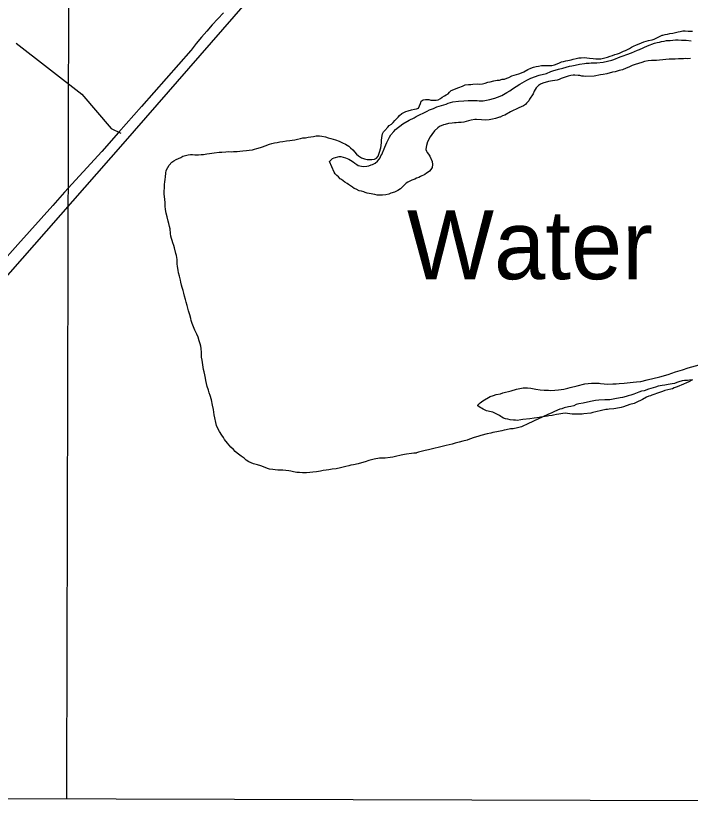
# Model space of a CAD drawing. Extents: x 3161514 to 3199414, y 831166 to 856601.
# Drawn here: x 3191795 to 3192773, y 836546 to 837696 of the extents above; entities that cross this region are included whole.
import ezdxf

# ---------------------------------------------------------------- set-up
doc = ezdxf.new("R2010")
doc.units = 0
for name, color, linetype in [('V-GRID-FRAM', 7, 'Continuous'), ('V-GRID-MAJR', 7, 'Continuous'), ('V-RIVR-IDEN', 7, 'Continuous'), ('V-ROAD-CNTR', 7, 'Continuous'), ('V-SITE-VEGE', 7, 'Continuous'), ('V-TOPO-SHOR', 7, 'Continuous')]:
    doc.layers.add(name, color=color, linetype=linetype)

msp = doc.modelspace()

# ---------------------------------------------------------------- linework, layer by layer
at = {"layer": 'V-GRID-FRAM'}
msp.add_lwpolyline([(3165761, 854820), (3197144.3, 854733.3), (3197102, 836546.1), (3165702.9, 836632.9), (3165761, 854820)], dxfattribs=at)
at = {"layer": 'V-GRID-MAJR'}
msp.add_spline([(3191868.8, 836560.6), (3191883.8, 842621), (3191898.8, 848683.4), (3191913.8, 854745.9), (3191913.8, 854747.8)], degree=3, dxfattribs=at)
at = {"layer": 'V-ROAD-CNTR'}
msp.add_lwpolyline([(3191529.5, 837031.7), (3191950.4, 837510.3), (3192561.4, 838211.2)], dxfattribs=at)
at = {"layer": 'V-SITE-VEGE'}
for points in [[(3192256.6, 837469), (3192250, 837484.8), (3192251.5, 837486.7), (3192254.3, 837488.9), (3192256.3, 837490), (3192263.6, 837491.9), (3192266.4, 837491.9), (3192273.1, 837489.8), (3192277.9, 837488.1), (3192280.1, 837486.6), (3192284, 837484.3), (3192286.5, 837482.3), (3192289.3, 837480.3), (3192291.5, 837478.9), (3192293.7, 837478.3), (3192298.5, 837477.4), (3192304.1, 837477.9), (3192306.6, 837478.4), (3192310.3, 837479.5), (3192312.3, 837480.3), (3192315.9, 837482.2), (3192319.3, 837485), (3192321.6, 837487.8), (3192323, 837489.7), (3192324.2, 837492.8), (3192325.6, 837494.7), (3192330.2, 837505.3), (3192332.9, 837512), (3192334.3, 837515.1), (3192336.6, 837519.6), (3192338.6, 837523.2), (3192342.9, 837528.2), (3192345.4, 837530.7), (3192356.2, 837539), (3192365.5, 837544.4), (3192372.6, 837548), (3192375.4, 837549.9), (3192391.2, 837557.3), (3192394.6, 837559.2), (3192400.8, 837561.4), (3192405.6, 837563.6), (3192412.4, 837565.7), (3192419.1, 837567.6), (3192421.6, 837569), (3192428.4, 837570.8), (3192436.6, 837572.1), (3192444.7, 837572.6), (3192450.6, 837572.8), (3192454, 837572.8), (3192459, 837573), (3192464, 837572.9), (3192466.6, 837572.6), (3192472.5, 837572.3), (3192482.3, 837574.4), (3192487.4, 837575.7), (3192489.6, 837576.5), (3192493.3, 837577.6), (3192499.5, 837580.3), (3192504.3, 837583.3), (3192506.8, 837584.4), (3192511.1, 837586.9), (3192515.3, 837589.7), (3192525.8, 837596.8), (3192528.9, 837598.5), (3192535.7, 837602.6), (3192541.9, 837605.3), (3192554, 837609.6), (3192564.4, 837612), (3192570.9, 837614.8), (3192573.7, 837615.8), (3192581.6, 837618.3), (3192588.1, 837619.6), (3192597.9, 837622.5), (3192601, 837623.1), (3192605.8, 837624.4), (3192612.2, 837625.4), (3192619.3, 837626.8), (3192622.1, 837627), (3192626.3, 837626.9), (3192629.1, 837627.5), (3192633.9, 837627.7), (3192637.5, 837627.6), (3192646.5, 837628.7), (3192659.2, 837631.6), (3192662, 837632.4), (3192671.3, 837636.2), (3192675.5, 837637.5), (3192680.9, 837639.7), (3192687.6, 837641.9), (3192696.4, 837646), (3192699.2, 837647.1), (3192710.8, 837652), (3192720.9, 837655.8), (3192725.1, 837656.8), (3192728.2, 837657.3), (3192731.3, 837658.4), (3192735.2, 837658.9), (3192738.6, 837659.7), (3192743.7, 837660), (3192751.5, 837660.7), (3192755.2, 837660.9)], [(3192755.2, 837660.9), (3192760.2, 837660.6), (3192763.9, 837660.5), (3192767, 837660.2), (3192774, 837659.3)], [(3192773.3, 837633.8), (3192769.1, 837633.5), (3192765.8, 837633.6), (3192763, 837633.3), (3192755.7, 837633.2), (3192751.2, 837632.9), (3192748.4, 837633), (3192744.7, 837632.7), (3192742.5, 837632.8), (3192728.4, 837631.3), (3192723.9, 837631), (3192721.7, 837631.1), (3192719.2, 837630.8), (3192716.9, 837630.8), (3192711.6, 837630.4), (3192706.5, 837629.3), (3192702.6, 837628.2), (3192693, 837625.3), (3192688.8, 837623.6), (3192684, 837621.4), (3192680.1, 837619.8), (3192674.4, 837617.6), (3192669.6, 837616.3), (3192667.1, 837615.5), (3192664, 837614.7), (3192660.1, 837613.9), (3192651.9, 837611.8), (3192646.6, 837610.7), (3192642.9, 837610.2), (3192633.6, 837608.3), (3192621.6, 837607.7), (3192617.9, 837608), (3192615.7, 837608.3), (3192612.9, 837609.2), (3192610.1, 837609.2), (3192605.3, 837609.5), (3192603.1, 837609.6), (3192599.7, 837609.1), (3192595.8, 837608), (3192585.6, 837604.7)], [(3192585.6, 837604.7), (3192582.8, 837603.4), (3192580, 837602.6), (3192573.2, 837601.3), (3192567.1, 837600.5), (3192558.9, 837598.1), (3192555.5, 837596.7), (3192553, 837594.8), (3192549.5, 837591.2), (3192546.4, 837586.5), (3192545, 837582.8), (3192539.8, 837574.8), (3192538.9, 837572.5), (3192535.5, 837568.9), (3192533.8, 837567.3), (3192531.3, 837565.3), (3192524.5, 837562.1), (3192519.7, 837560.1), (3192517.2, 837558.8), (3192512.1, 837556.6), (3192504.2, 837551.9), (3192500.5, 837550.6), (3192497.1, 837548.9), (3192496.3, 837548.7), (3192494.6, 837548.4), (3192490.6, 837546.8), (3192486.1, 837545.7), (3192481.1, 837544.9), (3192475.7, 837544.4), (3192470.4, 837544.8), (3192463.1, 837545.4), (3192460.3, 837545.5), (3192455.3, 837544.4), (3192451.3, 837543.3), (3192447.7, 837542.6), (3192444.6, 837541.8), (3192440.6, 837541.2), (3192436.7, 837541), (3192433.3, 837540.5), (3192430.8, 837540.5), (3192427.7, 837540), (3192422.1, 837539.5), (3192417.3, 837538.2), (3192415.1, 837537.6), (3192409.4, 837535.5), (3192406.9, 837533.5), (3192402.1, 837528.8), (3192398.1, 837523.6), (3192395.8, 837520.2), (3192392.1, 837513.3), (3192390.3, 837507.9), (3192389.7, 837505.1), (3192389.4, 837501.8), (3192390.2, 837499.5), (3192391.3, 837497.6), (3192393.5, 837495), (3192395.1, 837492.5), (3192398.4, 837484.8), (3192398.9, 837480.4), (3192398.6, 837476.1), (3192396.9, 837473.1), (3192394.6, 837470.6), (3192392.6, 837468.9), (3192390.6, 837467.8), (3192387.8, 837465.9), (3192381.6, 837462.6), (3192379.3, 837461.2), (3192376, 837460.2), (3192373.4, 837459.1), (3192369.2, 837457.4), (3192363.3, 837454.4), (3192361, 837453.1), (3192357.6, 837450), (3192352.5, 837445), (3192348.8, 837442.6), (3192344, 837440.1), (3192338.6, 837438.5), (3192335.8, 837437.4), (3192331.6, 837436.1), (3192326.8, 837435.6), (3192322.6, 837435.6), (3192319, 837435.9), (3192315.6, 837436.8), (3192307.5, 837438), (3192304.2, 837438.9), (3192301.4, 837439.5), (3192299.4, 837440.4), (3192296.1, 837441.6), (3192293, 837442.2), (3192288.2, 837444.7), (3192285.7, 837445.6), (3192282.9, 837447.3), (3192277.4, 837451), (3192275.2, 837452.8), (3192272.1, 837454.8), (3192267.1, 837458.5), (3192265.2, 837459.6), (3192262.7, 837462.2), (3192260.2, 837464.4), (3192258.2, 837466.7), (3192256.6, 837469)], [(3192496.4, 837116.5), (3192486.6, 837121.1), (3192484.4, 837121.7), (3192477.4, 837123.1), (3192472.4, 837125.5), (3192470.2, 837126.9), (3192468.2, 837128.3), (3192464.9, 837130.3), (3192464.9, 837131.2), (3192466.3, 837132.8), (3192468.3, 837134.8), (3192472.3, 837137.8), (3192482.7, 837143.8), (3192487.8, 837145.7), (3192491.4, 837146.8), (3192497.6, 837148.1), (3192501.3, 837149.2), (3192513.1, 837152.1), (3192521, 837154.6), (3192530.6, 837156.4), (3192536.7, 837156.6), (3192541.8, 837156.3), (3192548.8, 837154.8), (3192555.2, 837153.6), (3192561.1, 837153.2), (3192567.3, 837153.1), (3192570, 837152.8), (3192576.5, 837153.3), (3192581.6, 837153.5), (3192589.7, 837154.8), (3192595.3, 837155.9), (3192598.7, 837156.9), (3192608.8, 837159.6), (3192620.1, 837162.3), (3192629.9, 837163.6), (3192640.6, 837163.4), (3192642.5, 837162.8), (3192653.5, 837162.1), (3192660.8, 837162.6), (3192665.5, 837162.5), (3192670, 837163), (3192676.8, 837163.5), (3192681.5, 837163.7), (3192690.2, 837164.8), (3192694.7, 837165.5), (3192701.2, 837166), (3192710.5, 837168.1), (3192728.8, 837172.7), (3192740.9, 837175.9), (3192751.6, 837179.7), (3192761.7, 837182.6), (3192769.6, 837185.6), (3192785.6, 837189.9)], [(3192776.1, 837168.1), (3192771, 837165.4), (3192759.8, 837160.5), (3192759.5, 837160.5), (3192757.5, 837159.4), (3192754.1, 837158.1), (3192749.6, 837156.4), (3192747.1, 837155.3), (3192744.5, 837154.5), (3192740.3, 837153.5), (3192736.1, 837152.7), (3192732.4, 837151.3), (3192728.2, 837150), (3192717.2, 837145.9), (3192715, 837144.8), (3192713, 837144.3), (3192709.6, 837142.9), (3192703.4, 837139.9), (3192694.6, 837135.2), (3192691.3, 837133.9), (3192685.1, 837132.3), (3192676.3, 837129.3), (3192672.7, 837128.2), (3192670.4, 837127.7), (3192662, 837126.4), (3192655.3, 837125.9), (3192652.7, 837125.4), (3192650.5, 837125.2), (3192644, 837123.8), (3192636.1, 837121.7), (3192631.6, 837120.9), (3192628.5, 837120.1), (3192618.7, 837118.8), (3192616.2, 837118.6), (3192613.9, 837118.6), (3192610.3, 837118.4), (3192601.6, 837118.5), (3192594.9, 837119.4), (3192591.8, 837120), (3192588.1, 837119.5), (3192582.5, 837118.4), (3192578.9, 837117.9), (3192574.6, 837117.1), (3192572.7, 837116.6), (3192567.9, 837116.1), (3192565.9, 837115.6), (3192555.8, 837114), (3192553.8, 837113.5), (3192550.2, 837113.2), (3192546.3, 837112.7), (3192540.1, 837111.7), (3192530.2, 837110.7), (3192527.4, 837110.2), (3192521.8, 837109.4), (3192519.3, 837109.7), (3192516.5, 837109.7), (3192511.5, 837110.4), (3192508.4, 837111.3), (3192505, 837111.9), (3192502.2, 837112.7), (3192499.7, 837113.9), (3192498.1, 837115), (3192496.4, 837116.5)]]:
    msp.add_lwpolyline(points, dxfattribs=at)
at = {"layer": 'V-TOPO-SHOR'}
for points in [[(3192096, 837699.9), (3192087.8, 837691.3), (3192079.7, 837682.5), (3192071.9, 837673.6), (3192064.1, 837664.6), (3192056.6, 837655.4), (3192049.2, 837646.1), (3192048.5, 837645.2), (3192048.5, 837645.2), (3191977.4, 837564.5), (3191977.4, 837564.5), (3191943.7, 837526.7), (3191919.7, 837499), (3191892.4, 837469.7), (3191865.6, 837440), (3191848.8, 837420.9), (3191848.8, 837420.9), (3191797.8, 837364.5), (3191771, 837334.2)], [(3192632, 837633.9), (3192636.1, 837633.4), (3192639.7, 837633.1), (3192643.4, 837633.1), (3192647.3, 837634.2), (3192652.7, 837635.7), (3192656.9, 837637), (3192660.1, 837638.3), (3192663.7, 837639.4), (3192667.2, 837640.5), (3192670.4, 837641.6), (3192676.1, 837644.3), (3192678.9, 837645.6), (3192684.8, 837648.5), (3192687.8, 837650.1), (3192690.6, 837651.6), (3192694.9, 837653.6), (3192698.6, 837655.2), (3192702, 837656.7), (3192705.7, 837657.8), (3192708.7, 837658.7), (3192712.5, 837659.8), (3192717.6, 837661.1), (3192720.5, 837662), (3192726.5, 837664.6), (3192730, 837666.6), (3192732.2, 837667.5), (3192732.9, 837667.7), (3192736.4, 837668.8), (3192739.8, 837669.2), (3192743.4, 837670.1), (3192747.6, 837670.7), (3192751.7, 837671.4), (3192755.1, 837672.5), (3192758.3, 837673.1), (3192762, 837673.8), (3192765.4, 837673.9), (3192769.7, 837673.6), (3192775.9, 837673.3)], [(3191795.4, 837656.2), (3191890.8, 837581.9), (3191933.3, 837532.4), (3191947.4, 837525.4)], [(3192289, 837495.1), (3192291.7, 837492.6), (3192296.2, 837490), (3192300.7, 837488.4), (3192304.6, 837487.4), (3192311, 837487.3), (3192315.1, 837488), (3192318.1, 837489.5), (3192320.4, 837492.5), (3192322.3, 837497.9), (3192324, 837504.5), (3192324.5, 837507.9), (3192325.2, 837512), (3192325.2, 837515.2), (3192325.8, 837519.5), (3192326.7, 837524.5), (3192328.1, 837527.5), (3192330.2, 837529.7), (3192334.4, 837534.2), (3192336.5, 837536.5), (3192339.9, 837538.5), (3192342, 837541.2), (3192344.3, 837543.9), (3192346.6, 837545.9), (3192349.4, 837548.8), (3192351.2, 837551.3), (3192354.5, 837554), (3192357.4, 837555.8), (3192360.6, 837556.9), (3192363.9, 837558.2), (3192368.7, 837559.3), (3192372.8, 837560.2), (3192375.7, 837561), (3192378.9, 837561.7), (3192381.8, 837568.7), (3192382.5, 837572.1), (3192385.7, 837573.7), (3192388.9, 837574.3), (3192393.7, 837574.3), (3192396.9, 837573.5), (3192401.2, 837573.3), (3192404.4, 837573.4), (3192407.4, 837574.1), (3192410.8, 837575.9), (3192413.3, 837577.7), (3192416.3, 837579.7), (3192419.1, 837581), (3192421.6, 837582.8), (3192423.9, 837585), (3192426.2, 837587.5), (3192429.9, 837589.1), (3192433.6, 837590.4), (3192437.5, 837591.9), (3192442.5, 837593.9), (3192446.6, 837595.7), (3192451.4, 837596.3), (3192454.6, 837596.1), (3192457.8, 837596.5), (3192463.7, 837596.9), (3192466.9, 837596.8), (3192471.5, 837597), (3192475.6, 837598.1), (3192479.5, 837599.4), (3192482.5, 837600), (3192488, 837601.6), (3192493, 837602.4), (3192496.4, 837602.6), (3192500.1, 837603.7), (3192503.3, 837604.1), (3192506.9, 837605.2), (3192509.9, 837606.5), (3192514.3, 837608.5), (3192517.5, 837609.8), (3192524.3, 837611.4), (3192528, 837612.9), (3192531.7, 837614.7), (3192537.2, 837617.8), (3192541.5, 837620), (3192545.4, 837621.3), (3192549.5, 837622.2), (3192552.7, 837622.8), (3192557.3, 837623.5), (3192561.6, 837623.6), (3192567.8, 837623.6), (3192572.1, 837623.5), (3192575.8, 837624.6), (3192580.1, 837626.1), (3192583.3, 837627.7), (3192586.1, 837629), (3192589.3, 837629.7), (3192592.5, 837630.3), (3192595.5, 837631), (3192600, 837632), (3192603, 837632.7), (3192607.6, 837633.8), (3192611.2, 837634.6), (3192614.7, 837635), (3192619.9, 837635.2), (3192623.1, 837634.9), (3192627, 837634.2), (3192632, 837633.9)], [(3192029.5, 837332.3), (3192029.1, 837336.4), (3192028.8, 837342.8), (3192027.9, 837348.2), (3192027.1, 837351.4), (3192024.9, 837359.7), (3192024, 837362.9), (3192022.5, 837366.8), (3192021.8, 837370), (3192020.7, 837372.9), (3192019.9, 837376.6), (3192019.4, 837380), (3192018.6, 837387.1), (3192018, 837390.5), (3192016.9, 837394.9), (3192016, 837397.9), (3192014.3, 837404.5), (3192013, 837409.7), (3192011.9, 837415.2), (3192011.5, 837420), (3192011.4, 837425.3), (3192011, 837429.6), (3192010.6, 837433.9), (3192010.1, 837437.1), (3192010.2, 837441.7), (3192010.5, 837446.5), (3192010.5, 837451), (3192011.1, 837455.1), (3192011.3, 837458.3), (3192012.1, 837462.4), (3192012.4, 837467.9), (3192013.1, 837471.7), (3192015.2, 837476), (3192017.3, 837479.2), (3192021, 837483.5), (3192024.2, 837485.7), (3192027.4, 837487.3), (3192030.9, 837489.1), (3192034.1, 837490.4), (3192037.3, 837492.2), (3192040.9, 837493.3), (3192044.8, 837494.4), (3192048, 837494.8), (3192051.2, 837494.7), (3192054.6, 837494.2), (3192059.9, 837494.2), (3192063.8, 837494.6), (3192066.9, 837494.8), (3192072, 837495.6), (3192075.6, 837496.3), (3192079.1, 837496.7), (3192082.5, 837497.1), (3192090, 837498.1), (3192093.7, 837498.3), (3192099.4, 837498.7), (3192103, 837498.9), (3192107.6, 837498.8), (3192110.8, 837499), (3192115.8, 837499.2), (3192119.7, 837499.6), (3192124.2, 837500), (3192129.2, 837500.4), (3192133.4, 837500.8), (3192137.9, 837501.6), (3192140.9, 837502.5), (3192144.6, 837503.4), (3192149.6, 837504.9), (3192152.8, 837505.8), (3192156.7, 837507.3), (3192162.9, 837509.5), (3192166.1, 837510.6), (3192170, 837511.7), (3192173.8, 837512.1), (3192177.7, 837513), (3192182.1, 837513.6), (3192187.6, 837514.7), (3192192.3, 837515.1), (3192195.5, 837515.5), (3192199.7, 837516.1), (3192203.3, 837516.7), (3192207.9, 837517.8), (3192211.3, 837518.7), (3192215, 837519.1), (3192218.8, 837519.7), (3192222.5, 837520.1), (3192226.6, 837521), (3192230.5, 837521.6), (3192235.3, 837521.6), (3192238.7, 837521.5), (3192244.2, 837520.1), (3192247.8, 837519.1), (3192251.6, 837517.7), (3192255.3, 837516.8), (3192258.5, 837516), (3192263.9, 837513.9), (3192268.4, 837511.6), (3192273.2, 837509.5), (3192277.7, 837506.7), (3192280.4, 837504.6), (3192283.6, 837501.4), (3192289, 837495.1)], [(3192301.3, 837049.3), (3192296.3, 837047.8), (3192291.2, 837046.5), (3192284.6, 837045), (3192280.7, 837044.4), (3192277.8, 837043.7), (3192273.4, 837042.6), (3192269.8, 837041.8), (3192265.9, 837040.9), (3192259.2, 837039.4), (3192253.8, 837038.5), (3192248.7, 837037.7), (3192245.1, 837037.1), (3192240.5, 837036.7), (3192236.9, 837036), (3192233.7, 837035.6), (3192230.7, 837035), (3192225.7, 837034.3), (3192221.3, 837033.7), (3192216.3, 837033.6), (3192210.8, 837033.6), (3192206.5, 837033.7), (3192202.6, 837034), (3192197.6, 837034.9), (3192193.8, 837035.7), (3192190.6, 837036.2), (3192186.5, 837036.9), (3192182.2, 837037.2), (3192174.9, 837037.5), (3192170.8, 837038), (3192167.4, 837038.3), (3192163, 837038.6), (3192159.9, 837039.7), (3192154.2, 837042.3), (3192150.3, 837043.7), (3192145.3, 837044.9), (3192139.7, 837046.6), (3192136.3, 837047.8), (3192132.9, 837049.4), (3192128.8, 837052), (3192125.9, 837054.5), (3192121.8, 837057.6), (3192116.1, 837061.7), (3192113, 837064.5), (3192110.5, 837067.3), (3192106.7, 837070.5), (3192104.2, 837073.5), (3192101.7, 837076.5), (3192097.5, 837081.8), (3192095.9, 837084.5), (3192093.5, 837087.8), (3192090.1, 837093.5), (3192088.1, 837096.7), (3192085.9, 837102.2), (3192084.8, 837106.6), (3192083.3, 837113.2), (3192082.7, 837117.3), (3192081.4, 837125.1), (3192080.1, 837131.3), (3192078.6, 837139.2), (3192076.9, 837145.4), (3192075.5, 837149.5), (3192074.2, 837153.4), (3192072.5, 837158.5), (3192070.5, 837167.2), (3192070.1, 837170.4), (3192069, 837175.6), (3192068.2, 837179.7), (3192067.1, 837183.4), (3192066.7, 837186.6), (3192065.6, 837193.4), (3192065.2, 837196.6), (3192064.4, 837201.2), (3192064, 837207.6), (3192063.8, 837213.7), (3192063.2, 837216.9), (3192062.3, 837220.4), (3192061, 837224.7), (3192059.2, 837229.8), (3192057.3, 837234.6), (3192054.4, 837240.3), (3192052.4, 837244.9), (3192050.6, 837249.7), (3192049.3, 837254.3), (3192048.7, 837257.2), (3192047.1, 837262.3), (3192045.1, 837268.2), (3192043.4, 837275.8), (3192042.1, 837280.6), (3192041, 837284.5), (3192039.5, 837289.3), (3192038.4, 837293.9), (3192037.5, 837297.7), (3192036.2, 837302.1), (3192035.4, 837305.5), (3192034.3, 837309.6), (3192033.6, 837312.8), (3192032.3, 837318.3), (3192031, 837323.4), (3192030.2, 837327.2), (3192029.5, 837332.3)], [(3192774.2, 837168.2), (3192768.7, 837167.4), (3192764.6, 837167), (3192761.2, 837166.6), (3192756.4, 837165.3), (3192753.4, 837164.2), (3192749.8, 837163.1), (3192746.6, 837162.4), (3192740.6, 837161.4), (3192736, 837160.5), (3192732.2, 837159.9), (3192726.5, 837159), (3192722.3, 837157.5), (3192718.9, 837156.4), (3192715.7, 837155.5), (3192712.5, 837154.7), (3192705.9, 837152.2), (3192702.4, 837151.6), (3192698.5, 837150.1), (3192691.2, 837147.4), (3192686.6, 837145.9), (3192683, 837145), (3192679.8, 837144.1), (3192674.7, 837142.6), (3192671.1, 837142), (3192663.3, 837140.5), (3192656.2, 837139.4), (3192652.6, 837139.2), (3192648.9, 837139.1), (3192640.5, 837138.9), (3192635.7, 837138.3), (3192630.7, 837137.5), (3192623.8, 837136), (3192617.4, 837134.4), (3192611.5, 837133.2), (3192607.6, 837132.3), (3192603.9, 837130.7), (3192599.6, 837129.4), (3192596.4, 837129), (3192590.2, 837127.5), (3192586.8, 837126.4), (3192583.6, 837125.8), (3192580.6, 837124.2), (3192574.9, 837121.8), (3192571, 837120), (3192567.5, 837118.4), (3192564.5, 837116.9), (3192560.9, 837115.3), (3192557.9, 837114), (3192551.7, 837111.1), (3192546.6, 837108.7), (3192543.7, 837107.3), (3192538.2, 837104.9), (3192528.1, 837100.2), (3192522.4, 837098.5), (3192516, 837097.2), (3192512.1, 837097), (3192506.1, 837095.7), (3192502.9, 837095.1), (3192499.7, 837094.2), (3192492.4, 837092.7), (3192486.7, 837091.7), (3192483.5, 837091), (3192478.5, 837089.9), (3192469.1, 837087.6), (3192464.8, 837086), (3192459.7, 837084.5), (3192452.6, 837082.1), (3192449.4, 837081), (3192443, 837079.2), (3192437.8, 837077.7), (3192432, 837076.2), (3192427.7, 837075.1), (3192423.3, 837073.8), (3192418.8, 837072.9), (3192411.2, 837071), (3192407.3, 837070.1), (3192402.8, 837069), (3192393.2, 837066.9), (3192388.6, 837065.8), (3192384.5, 837064.7), (3192379, 837063.2), (3192376, 837062.3), (3192375.3, 837062.1), (3192372.1, 837061.9), (3192368.5, 837061.5), (3192361.6, 837060.4), (3192358.4, 837060), (3192353.6, 837058.9), (3192345.4, 837057), (3192341.5, 837056.1), (3192337.9, 837055.5), (3192330.3, 837054.9), (3192326, 837054.5), (3192322.3, 837054.5), (3192314.3, 837053.3), (3192306.8, 837051.5), (3192301.3, 837049.3)]]:
    msp.add_lwpolyline(points, dxfattribs=at)

# ---------------------------------------------------------------- texts
at = {"layer": 'V-RIVR-IDEN'}
msp.add_text('Water', height=100, dxfattribs=at).set_placement((3192362.1, 837314))

doc.saveas('drawing.dxf')
